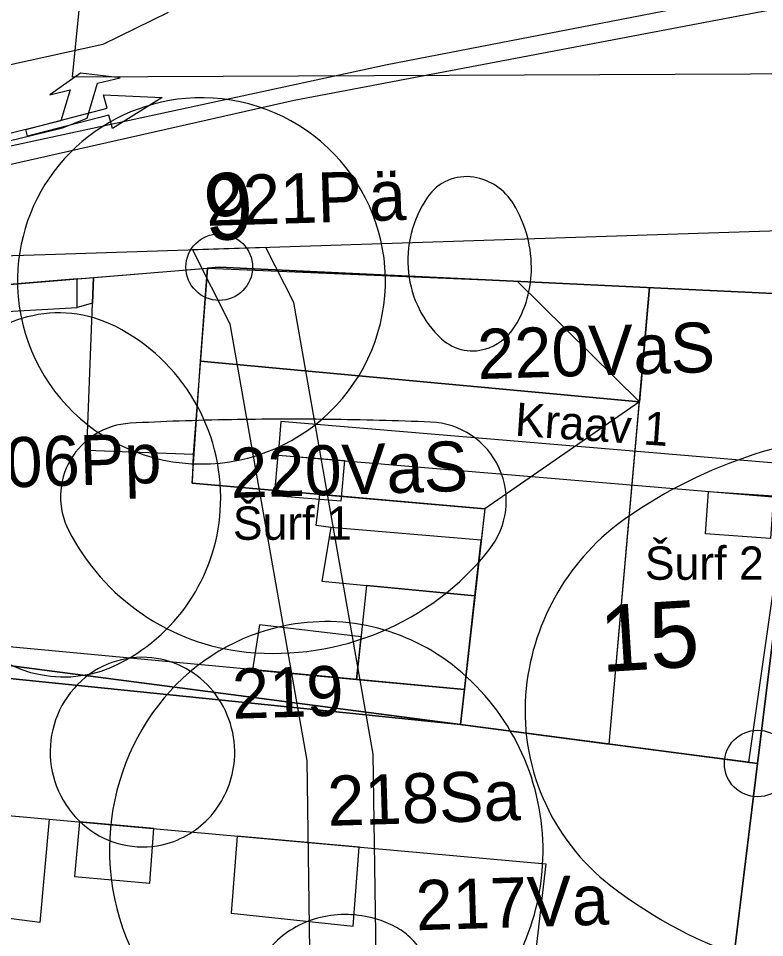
# Model space of a CAD drawing. Extents: x 738423 to 738903, y 6589762 to 6590172.
# Drawn here: x 738614.31 to 738636.72, y 6589921.66 to 6589949.26 of the extents above; entities that cross this region are included whole.
import ezdxf

# ---------------------------------------------------------------- set-up
doc = ezdxf.new("R2010")
doc.units = 0
for name, color, linetype in [('_1927_hoonestus', 7, 'Continuous'), ('_1927_katuse_kalded', 7, 'Continuous'), ('_1927_koordin_punktid_nr', 7, 'Continuous'), ('_1927_krundi_piir', 7, 'Continuous'), ('_1927_uhepoolne_katusekalle', 7, 'Continuous'), ('_ajalooline_liivavall_linnamuur', 7, 'Continuous'), ('_arheol_Rüütli8_tekst', 7, 'Continuous'), ('_arheol_Rüütli8_tranžee', 7, 'Continuous'), ('a_dendro_II_Vkl_puu', 7, 'Continuous'), ('a_dendro_III_vk_puu', 7, 'Continuous'), ('a_dendro_puu_nr', 7, 'Continuous'), ('a_dendro_V_vk_puu', 7, 'Continuous'), ('Default', 7, 'Continuous'), ('plan_ala', 7, 'Continuous'), ('v_dp_jalak_liikumine', 7, 'Continuous'), ('v_olol_kitsendus_tehnov', 7, 'Continuous'), ('v_olol_sõidusuunad', 7, 'Continuous'), ('v_olol_transp_tee', 7, 'Continuous')]:
    doc.layers.add(name, color=color, linetype=linetype)

# ---------------------------------------------------------------- blocks, each defined once
blk = doc.blocks.new('_U670')
at = {"layer": 'Default'}
for centre, radius, start, end in [((-0.0007387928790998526, -0.0009499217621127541), 0.010951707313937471, 90.41401602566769, 137.4355023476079), ((-0.0007387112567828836, -0.0009612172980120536), 0.01096300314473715, 49.68529802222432, 90.41401602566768), ((-0.000816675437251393, -0.0010531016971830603), 0.011083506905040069, 9.188353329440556, 49.68529802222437), ((-0.0006442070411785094, -0.0010367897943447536), 0.011080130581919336, 137.43550234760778, 184.1674065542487), ((-0.0008241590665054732, -0.0010543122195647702), 0.011091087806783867, 324.0124918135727, 9.188353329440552), ((-0.0006391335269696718, -0.0010364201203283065), 0.011085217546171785, 184.1674065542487, 231.21741392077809), ((-0.0007216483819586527, -0.0011287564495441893), 0.010964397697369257, 278.5618692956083, 324.0124918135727), ((-0.0007203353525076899, -0.0011374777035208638), 0.010955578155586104, 231.217413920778, 278.5618692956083)]:
    blk.add_arc(centre, radius, start, end, dxfattribs=at)
blk = doc.blocks.new('_U668')
at = {"layer": 'Default'}
for centre, radius, start, end in [((0.0008747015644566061, -0.002814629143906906), 0.00678705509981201, 59.99182900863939, 100.44148396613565), ((0.000791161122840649, -0.0023613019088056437), 0.006326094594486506, 100.44148396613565, 141.431996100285), ((0.0028587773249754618, 0.0006207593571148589), 0.002819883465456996, 355.12377783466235, 59.99182900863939), ((-0.0020393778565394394, -0.00010429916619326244), 0.0027058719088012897, 141.43199610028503, 206.16822143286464), ((0.002252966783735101, 0.0006724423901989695), 0.003427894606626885, 305.6386944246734, 355.12377783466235), ((-0.0014425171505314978, 0.00018898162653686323), 0.0033708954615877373, 206.16822143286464, 245.19506184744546), ((-4.796887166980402e-05, 0.0038817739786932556), 0.007376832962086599, 272.4839108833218, 305.63869442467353), ((-2.1184452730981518e-05, 0.003264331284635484), 0.006758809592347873, 245.1950618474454, 272.4839108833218)]:
    blk.add_arc(centre, radius, start, end, dxfattribs=at)
blk = doc.blocks.new('_U655')
at = {"layer": 'Default'}
for centre, radius, start, end in [((0.0017439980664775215, -0.012298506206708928), 0.014456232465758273, 97.79638221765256, 115.4590201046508), ((0.0017671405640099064, -0.012467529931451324), 0.014626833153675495, 80.09489063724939, 97.79638221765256), ((0.0022104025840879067, -0.009929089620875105), 0.012049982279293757, 60.57553654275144, 80.09489063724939), ((0.0004945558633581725, -0.009674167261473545), 0.011549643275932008, 115.45902010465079, 135.23949598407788), ((0.0044404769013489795, -0.005975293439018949), 0.007510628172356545, 337.28207682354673, 60.575536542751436), ((-0.0024260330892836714, -0.006777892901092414), 0.007436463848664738, 135.23949598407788, 211.736455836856), ((0.0007064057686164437, -0.004411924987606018), 0.011558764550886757, 272.5027635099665, 337.2820768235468), ((0.0007246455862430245, -0.004829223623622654), 0.011141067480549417, 211.73645583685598, 272.5027635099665)]:
    blk.add_arc(centre, radius, start, end, dxfattribs=at)
blk = doc.blocks.new('_U672')
at = {"layer": 'Default'}
for centre, radius, start, end in [((-0.002101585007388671, 0.008719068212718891), 0.013254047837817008, 88.3470711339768, 146.6623908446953), ((-0.0021311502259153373, 0.007694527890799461), 0.014279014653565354, 39.22630250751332, 88.34707113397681), ((-0.01341153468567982, -0.0015141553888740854), 0.028840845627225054, 5.215032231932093, 39.22630250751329), ((0.010393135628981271, 0.000499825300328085), 0.02820978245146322, 146.6623908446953, 185.68101847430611), ((-0.013432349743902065, -0.0015160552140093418), 0.028861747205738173, 330.3262965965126, 5.215032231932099), ((0.010167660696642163, 0.0004773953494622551), 0.027983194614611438, 185.68101847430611, 223.49376727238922), ((-0.0006298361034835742, -0.008810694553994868), 0.014126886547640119, 279.58281790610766, 330.3262965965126), ((-0.0004907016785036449, -0.009634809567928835), 0.013291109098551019, 223.49376727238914, 279.5828179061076)]:
    blk.add_arc(centre, radius, start, end, dxfattribs=at)
blk = doc.blocks.new('_U651')
at = {"layer": 'Default'}
for centre, radius, start, end in [((0.00047664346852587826, 0.0003030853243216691), 0.005795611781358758, 49.93101198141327, 99.87682055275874), ((0.0004710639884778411, 0.0003351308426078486), 0.005763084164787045, 99.87682055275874, 149.09162522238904), ((0.0007179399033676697, 0.0005899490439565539), 0.00542075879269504, 358.1639607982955, 49.93101198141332), ((0.00016307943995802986, 0.0005195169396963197), 0.005404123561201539, 149.09162522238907, 200.02741080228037), ((0.000649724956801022, 0.0005921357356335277), 0.005489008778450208, 313.2341935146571, 358.1639607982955), ((0.0002363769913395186, 0.000546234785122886), 0.005482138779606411, 200.02741080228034, 235.3717727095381), ((0.0004126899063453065, 0.0008442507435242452), 0.005835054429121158, 269.72730137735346, 313.23419351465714), ((0.00041248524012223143, 0.0008012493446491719), 0.005792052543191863, 235.37177270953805, 269.72730137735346)]:
    blk.add_arc(centre, radius, start, end, dxfattribs=at)
blk = doc.blocks.new('_U666')
at = {"layer": 'Default'}
for centre, radius, start, end in [((0.00011899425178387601, -0.004345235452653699), 0.014377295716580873, 93.73643240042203, 132.97828326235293), ((0.00011601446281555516, -0.004299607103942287), 0.014331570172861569, 56.96948487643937, 93.73643240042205), ((0.0009683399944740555, -0.0029886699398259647), 0.012767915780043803, 17.930281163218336, 56.96948487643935), ((-0.0009846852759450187, -0.0031607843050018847), 0.012758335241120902, 132.9782832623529, 174.74476914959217), ((0.001317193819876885, -0.002875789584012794), 0.01240125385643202, 324.8404425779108, 17.930281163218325), ((-0.0013245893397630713, -0.0031295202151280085), 0.012416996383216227, 174.74476914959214, 226.8513130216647), ((-0.00011934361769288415, -0.0018639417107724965), 0.014158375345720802, 275.39216212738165, 324.8404425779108), ((-0.00012107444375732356, -0.001845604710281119), 0.014176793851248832, 226.85131302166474, 275.39216212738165)]:
    blk.add_arc(centre, radius, start, end, dxfattribs=at)
blk = doc.blocks.new('_U665')
at = {"layer": 'Default'}
for centre, radius, start, end in [((-0.0029044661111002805, 0.0034915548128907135), 0.0034719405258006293, 46.56687312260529, 144.94764569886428), ((-0.004520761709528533, 0.0017843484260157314), 0.005822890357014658, 15.60075044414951, 46.56687312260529), ((-0.0008804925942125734, 0.0020715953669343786), 0.005944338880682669, 144.94764569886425, 215.63059108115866), ((-0.005270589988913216, 0.0015749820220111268), 0.00660139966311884, 346.56064947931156, 15.600750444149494), ((-0.004259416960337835, 0.0013333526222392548), 0.005561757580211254, 334.10172837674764, 346.56064947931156), ((-0.003230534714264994, 0.0008337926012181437), 0.0044180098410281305, 320.11565064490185, 334.1017283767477), ((-0.002239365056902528, 0.0010976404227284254), 0.004272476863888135, 215.63059108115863, 264.0891552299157), ((-0.002343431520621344, 9.247083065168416e-05), 0.0032619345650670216, 264.0891552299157, 320.11565064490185)]:
    blk.add_arc(centre, radius, start, end, dxfattribs=at)
blk = doc.blocks.new('_U667')
at = {"layer": 'Default'}
for centre, radius, start, end in [((-0.004901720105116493, 0.005444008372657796), 0.004420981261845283, 7.392000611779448, 121.28846410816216), ((-0.00017901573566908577, -0.0023269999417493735), 0.013514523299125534, 121.28846410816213, 178.58051492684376), ((-0.1569009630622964, -0.01427566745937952), 0.15769405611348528, 6.325544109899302, 7.392000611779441), ((-0.1806114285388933, -0.016904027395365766), 0.18154975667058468, 5.331622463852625, 6.325544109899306), ((-0.19525593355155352, -0.01827070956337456), 0.19625789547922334, 3.6327563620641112, 5.331622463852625), ((0.002833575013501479, -0.002401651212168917), 0.01652803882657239, 178.58051492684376, 235.64850716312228), ((-0.21766428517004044, -0.019693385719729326), 0.2187113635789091, 2.0234622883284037, 3.6327563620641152), ((-0.003821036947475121, -0.012138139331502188), 0.00473469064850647, 235.64850716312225, 2.0234622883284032)]:
    blk.add_arc(centre, radius, start, end, dxfattribs=at)

msp = doc.modelspace()

# ---------------------------------------------------------------- linework, layer by layer
at = {"layer": '_1927_hoonestus'}
for points in [[(738616.5677014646, 6589941.483718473), (738619.9942934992, 6589941.7670035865), (738619.5589872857, 6589936.166617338), (738616.3669749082, 6589936.289981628)], [(738619.9942934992, 6589941.7670035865), (738619.5589872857, 6589936.166617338), (738619.5589872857, 6589936.166617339), (738619.5256598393, 6589935.304280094), (738628.31766578, 6589934.534553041), (738627.5826462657, 6589928.059372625), (738636.5091918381, 6589926.891104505), (738638.2396178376, 6589940.94571321), (738620.342268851, 6589941.795771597)], [(738613.9149701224, 6589941.264410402), (738613.9584355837, 6589940.464002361), (738616.0754039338, 6589940.578962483), (738616.0732181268, 6589941.442838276)], [(738616.0732181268, 6589941.442838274), (738616.5677014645, 6589941.483718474), (738616.538114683, 6589940.718169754), (738616.0754039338, 6589940.578962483)], [(738628.2116133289, 6589933.600280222), (738623.6897597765, 6589933.975535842), (738623.2530983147, 6589934.0341842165), (738623.3577777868, 6589934.968783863), (738628.31766578, 6589934.534553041)], [(738623.6897597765, 6589933.975535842), (738623.421921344, 6589932.366833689), (738628.0213326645, 6589931.923995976), (738628.211613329, 6589933.600280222)], [(738624.7684587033, 6589932.237187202), (738624.4683143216, 6589929.414598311), (738627.7020754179, 6589929.111487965), (738628.0213326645, 6589931.923995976)], [(738624.6048161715, 6589930.698275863), (738621.5461287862, 6589931.054018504), (738621.3388231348, 6589929.707935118), (738624.4683143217, 6589929.41459831)], [(738609.0967282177, 6589930.816042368), (738609.1142653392, 6589930.4764353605), (738627.5826462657, 6589928.059372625), (738627.7020754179, 6589929.111487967), (738612.2102685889, 6589930.563582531)], [(738609.1142653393, 6589930.4764353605), (738609.1419593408, 6589929.940140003), (738627.5826291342, 6589928.059374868)], [(738609.1419593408, 6589929.940140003), (738609.3368931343, 6589926.165239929), (738613.9533353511, 6589925.894244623), (738613.8912678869, 6589925.340685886), (738630.1483324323, 6589923.879602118), (738629.3435517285, 6589916.969136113), (738634.4211056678, 6589916.921415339), (738635.2838401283, 6589916.916987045), (738636.509191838, 6589926.891104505), (738627.5826462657, 6589928.059372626)], [(738613.891267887, 6589925.340685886), (738615.2310681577, 6589925.220272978), (738614.9522152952, 6589922.1175562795), (738613.5503822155, 6589922.300441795)], [(738616.1437892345, 6589925.138243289), (738615.9954149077, 6589923.500116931), (738618.255780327, 6589923.2953829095), (738618.3819230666, 6589924.9370937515)], [(738620.8824012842, 6589924.712366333), (738620.7046052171, 6589922.400570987), (738624.3619183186, 6589922.004749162), (738624.5386819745, 6589924.383762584)]]:
    msp.add_lwpolyline(points, close=True, dxfattribs=at)
at = {"layer": '_1927_katuse_kalded'}
for points in [[(738629.2909433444, 6589941.370742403), (738632.9569607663, 6589937.747719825), (738619.7766403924, 6589938.966810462), (738619.9942934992, 6589941.7670035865)], [(738629.2909433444, 6589941.370742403), (738633.2615524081, 6589941.182153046), (738632.9569607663, 6589937.747719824)], [(738633.2615524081, 6589941.182153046), (738638.2396178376, 6589940.94571321), (738636.2310283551, 6589926.927509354), (738632.0459190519, 6589927.475238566)], [(738632.9569607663, 6589937.747719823), (738628.3176657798, 6589934.534553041), (738619.5256598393, 6589935.304280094), (738619.7766403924, 6589938.96681046)], [(738632.9569607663, 6589937.747719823), (738628.31766578, 6589934.534553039), (738627.5826462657, 6589928.059372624), (738632.0459190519, 6589927.475238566)]]:
    msp.add_lwpolyline(points, close=True, dxfattribs=at)
at = {"layer": '_1927_koordin_punktid_nr'}
for centre in [(738620.342268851, 6589941.795771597), (738636.5091918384, 6589926.8911045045)]:
    msp.add_circle(centre, 0.9999999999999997, dxfattribs=at)
at = {"layer": '_1927_krundi_piir'}
msp.add_line((738609.1136156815, 6589930.476520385), (738636.5091918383, 6589926.8911045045), dxfattribs=at)
for points in [[(738586.182705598, 6589872.620611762), (738590.9372064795, 6589898.13516685), (738590.975352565, 6589898.488217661), (738593.7110525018, 6589923.115674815), (738595.6482555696, 6589940.609766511), (738608.5799562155, 6589940.823351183), (738620.342268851, 6589941.795771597), (738638.2396178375, 6589940.94571321)], [(738638.2396178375, 6589940.94571321), (738636.5091918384, 6589926.8911045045), (738634.3211426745, 6589909.080822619), (738629.2817413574, 6589868.018556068)]]:
    msp.add_lwpolyline(points, dxfattribs=at)
at = {"layer": '_1927_uhepoolne_katusekalle'}
msp.add_lwpolyline([(738616.5677014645, 6589941.483718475), (738619.9942934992, 6589941.7670035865), (738619.5589872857, 6589936.166617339), (738616.3669749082, 6589936.289981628)], close=True, dxfattribs=at)
at = {"layer": '_ajalooline_liivavall_linnamuur'}
msp.add_lwpolyline([(738708.289405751, 6589968.14747116), (738780.2257645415, 6589985.561122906), (738769.667506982, 6589952.525563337), (738767.8196994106, 6589945.734830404), (738713.208654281, 6589947.930212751), (738615.9368314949, 6589947.498858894), (738617.4577657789, 6589962.743100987), (738623.554579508, 6589962.319832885), (738622.8971321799, 6589952.276700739), (738711.4568073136, 6589955.13)], close=True, dxfattribs=at)
at = {"layer": '_arheol_Rüütli8_tranžee'}
for points in [[(738622.1085370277, 6589936.153210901), (738642.1870033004, 6589934.459372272), (738642.2717703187, 6589935.464185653), (738622.1933040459, 6589937.158024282)], [(738622.1085370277, 6589936.153210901), (738624.1003154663, 6589935.985182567), (738623.9972260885, 6589934.763179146), (738622.00544765, 6589934.931207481)], [(738635.0359158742, 6589935.06264485), (738636.9867592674, 6589934.925584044), (738636.8972313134, 6589933.651295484), (738634.9463879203, 6589933.788356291)]]:
    msp.add_lwpolyline(points, close=True, dxfattribs=at)
at = {"layer": 'plan_ala'}
msp.add_lwpolyline([(738772.2221966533, 6589837.873120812), (738583.11, 6589865.669999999), (738583.11, 6589865.669999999), (738577.13, 6589865.85), (738565.7035831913, 6589866.139410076), (738565.4500000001, 6589885.77), (738564.4932191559, 6589941.052825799), (738581.9, 6589941.1499999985), (738615.11, 6589942.169999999), (738650.0499999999, 6589943.319999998), (738691.2690631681, 6589944.800325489), (738696.0901513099, 6589944.851371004), (738713.89, 6589945.129999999), (738703.51, 6589987.789999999), (738752.8799999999, 6590000.39), (738783.1408503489, 6590007.463828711), (738767.5688789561, 6589951.87996157)], close=True, dxfattribs=at)
at = {"layer": 'v_dp_jalak_liikumine'}
msp.add_lwpolyline([(738578.970251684, 6589937.862152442), (738584.5045426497, 6589940.144760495), (738605.4024666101, 6589943.568672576), (738625.3859761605, 6589947.878936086), (738640.1312149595, 6589950.743854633), (738648.7056120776, 6589951.738200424), (738653.8672730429, 6589953.473473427), (738655.5881166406, 6589952.565697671), (738661.6250098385, 6589952.40725923), (738665.8485456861, 6589953.015650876), (738673.5708121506, 6589955.317894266), (738678.5915111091, 6589956.996715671), (738685.859941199, 6589956.947013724), (738690.3670481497, 6589963.134599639), (738692.7749703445, 6589968.674602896), (738694.4616114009, 6589968.262260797), (738695.9325192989, 6589968.635332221), (738697.285754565, 6589969.852723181), (738697.4340711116, 6589971.167063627), (738697.1595016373, 6589972.894973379), (738696.0808358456, 6589974.465800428), (738695.1786790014, 6589976.311522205), (738693.4626197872, 6589985.738938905), (738690.6242451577, 6589995.688458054)], dxfattribs=at)
at = {"layer": 'v_olol_kitsendus_tehnov'}
msp.add_lwpolyline([(738625.1699327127, 6589913.022275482), (738624.9687574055, 6589927.174521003), (738622.5792854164, 6589940.728419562), (738621.7434438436, 6589942.388330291), (738619.5407022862, 6589942.31583021), (738620.6607145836, 6589940.0915804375), (738622.9712425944, 6589926.985478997), (738623.1740351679, 6589912.719462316)], dxfattribs=at)
at = {"layer": 'v_olol_sõidusuunad'}
for points in [[(738617.3627720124, 6589947.480439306), (738616.1751192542, 6589947.622850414), (738615.2546753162, 6589946.96582457), (738615.8667033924, 6589947.115228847), (738615.58988726, 6589946.182988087), (738613.4817905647, 6589945.668373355), (738613.5315919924, 6589945.464363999), (738615.6396886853, 6589945.97897873), (738616.3713226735, 6589946.265663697), (738616.68274082, 6589947.3144345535)], [(738617.1332273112, 6589945.955235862), (738617.026732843, 6589946.361510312), (738614.5890861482, 6589945.722543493), (738614.5358389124, 6589945.92568072), (738616.9734856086, 6589946.564647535), (738616.8669911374, 6589946.970921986), (738618.6252070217, 6589946.889056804)]]:
    msp.add_lwpolyline(points, close=True, dxfattribs=at)
at = {"layer": 'v_olol_transp_tee'}
for points in [[(738584.657, 6589939.739), (738591.8759999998, 6589941.141000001), (738604.314, 6589942.948), (738608.7239999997, 6589943.676999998), (738622.5910000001, 6589946.809999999), (738640.784, 6589950.2689999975)], [(738618.8097714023, 6589949.440372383), (738616.848, 6589948.483999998), (738614.0769999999, 6589947.869999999), (738609.6759999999, 6589947.041999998), (738591.8079999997, 6589943.795), (738583.98, 6589942.533999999)]]:
    msp.add_lwpolyline(points, dxfattribs=at)

# ---------------------------------------------------------------- block references
at = {"layer": 'a_dendro_II_Vkl_puu', "xscale": 500.0000000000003, "yscale": 500.0000000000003, "rotation": 85.69234851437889}
msp.add_blockref('_U670', (738619.3140000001, 6589941.785), dxfattribs=at)
at = {"layer": 'a_dendro_III_vk_puu', "xscale": 500.0000000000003, "yscale": 500.0000000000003, "rotation": 85.69234851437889}
for name, p in [('_U672', (738640.577, 6589929.188)), ('_U666', (738622.0625, 6589924.4025))]:
    msp.add_blockref(name, p, dxfattribs=at)
at = {"layer": 'a_dendro_V_vk_puu', "xscale": 500.0000000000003, "yscale": 500.0000000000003, "rotation": 85.69234851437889}
for name, p in [('_U668', (738627.9639999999, 6589941.653)), ('_U655', (738612.38, 6589934.675)), ('_U667', (738620.685, 6589937.138999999)), ('_U651', (738618.2946732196, 6589926.989151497)), ('_U665', (738625.1120000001, 6589921.624))]:
    msp.add_blockref(name, p, dxfattribs=at)

# ---------------------------------------------------------------- texts
at = {"layer": '_1927_koordin_punktid_nr'}
for s, rotation, p in [('9', 3.560863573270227, (738619.932683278, 6589942.57974124)), ('15', 3.560863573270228, (738631.8302740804, 6589929.631636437))]:
    msp.add_text(s, height=1.9999999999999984, rotation=rotation, dxfattribs=at).set_placement(p)
at = {"layer": '_arheol_Rüütli8_tekst'}
for s, rotation, p in [('Kraav 1', 356.0887935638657, (738629.2012790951, 6589936.735644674)), ('Šurf 1', 359.99285992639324, (738620.7513093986, 6589933.608586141)), ('Šurf 2', 359.99285992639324, (738633.123128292, 6589932.408217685))]:
    msp.add_text(s, height=1.0000000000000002, rotation=rotation, dxfattribs=at).set_placement(p)
at = {"layer": 'a_dendro_puu_nr'}
for s, p in [('221P', (738619.961571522, 6589943.031393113)), ('ä', (738624.8532489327, 6589943.179831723)), ('220VaS', (738628.1104151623, 6589938.432359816)), ('206Pp', (738612.827310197, 6589935.144099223)), ('220VaS', (738620.6976279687, 6589934.86241192)), ('219', (738620.7488101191, 6589928.2333003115)), ('218Sa', (738623.610399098, 6589925.016915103)), ('217Va', (738626.261519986, 6589921.88235096))]:
    msp.add_text(s, height=1.5, rotation=1.7381147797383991, dxfattribs=at).set_placement(p)

doc.saveas('drawing.dxf')
